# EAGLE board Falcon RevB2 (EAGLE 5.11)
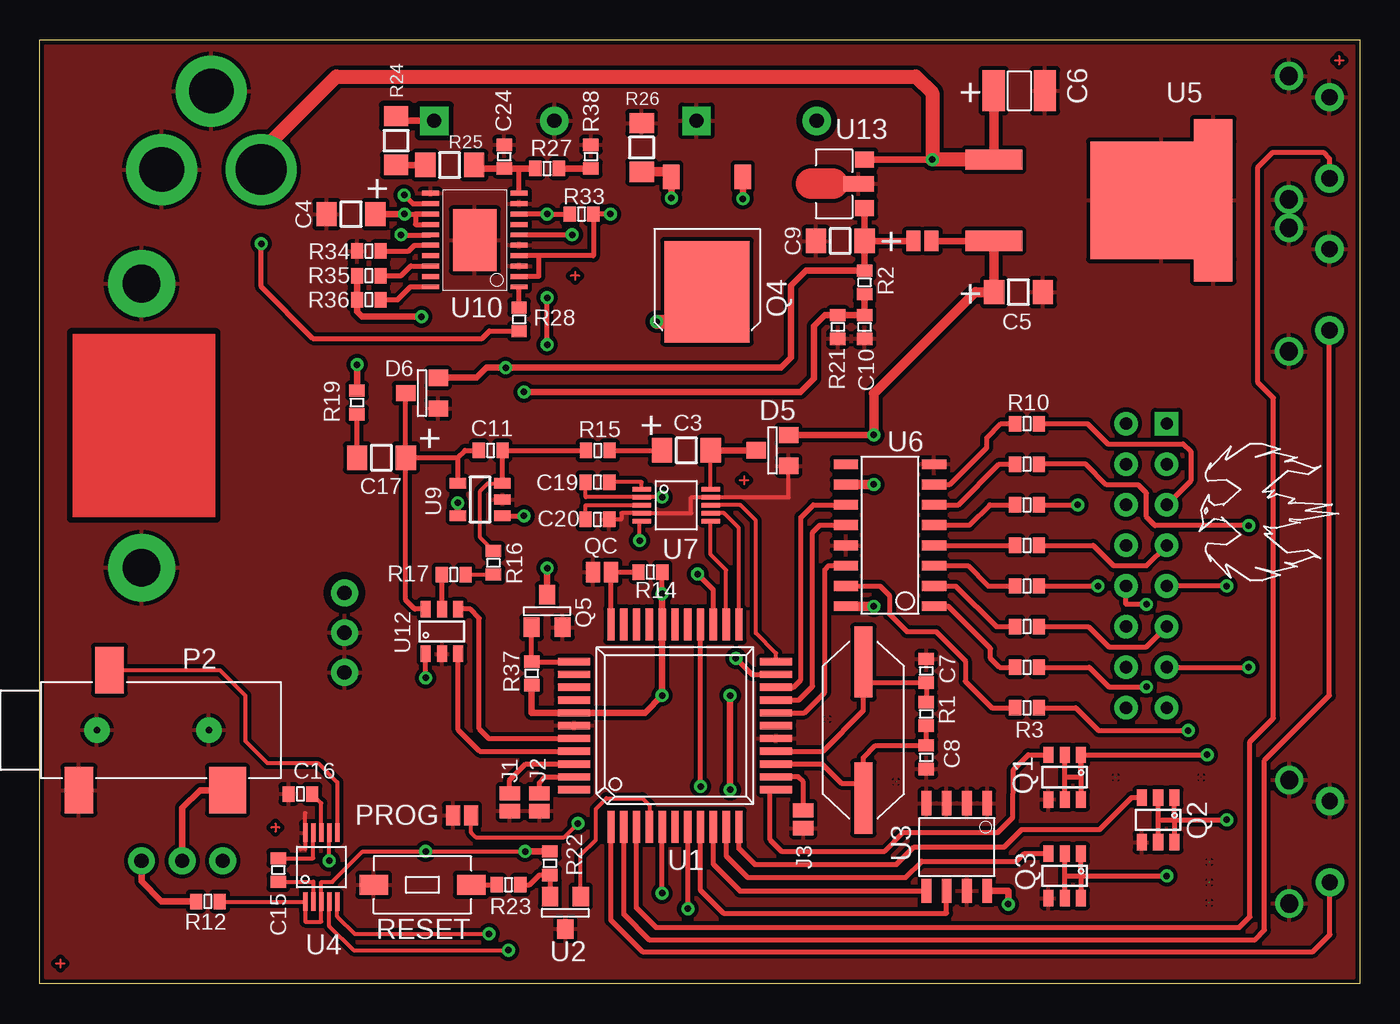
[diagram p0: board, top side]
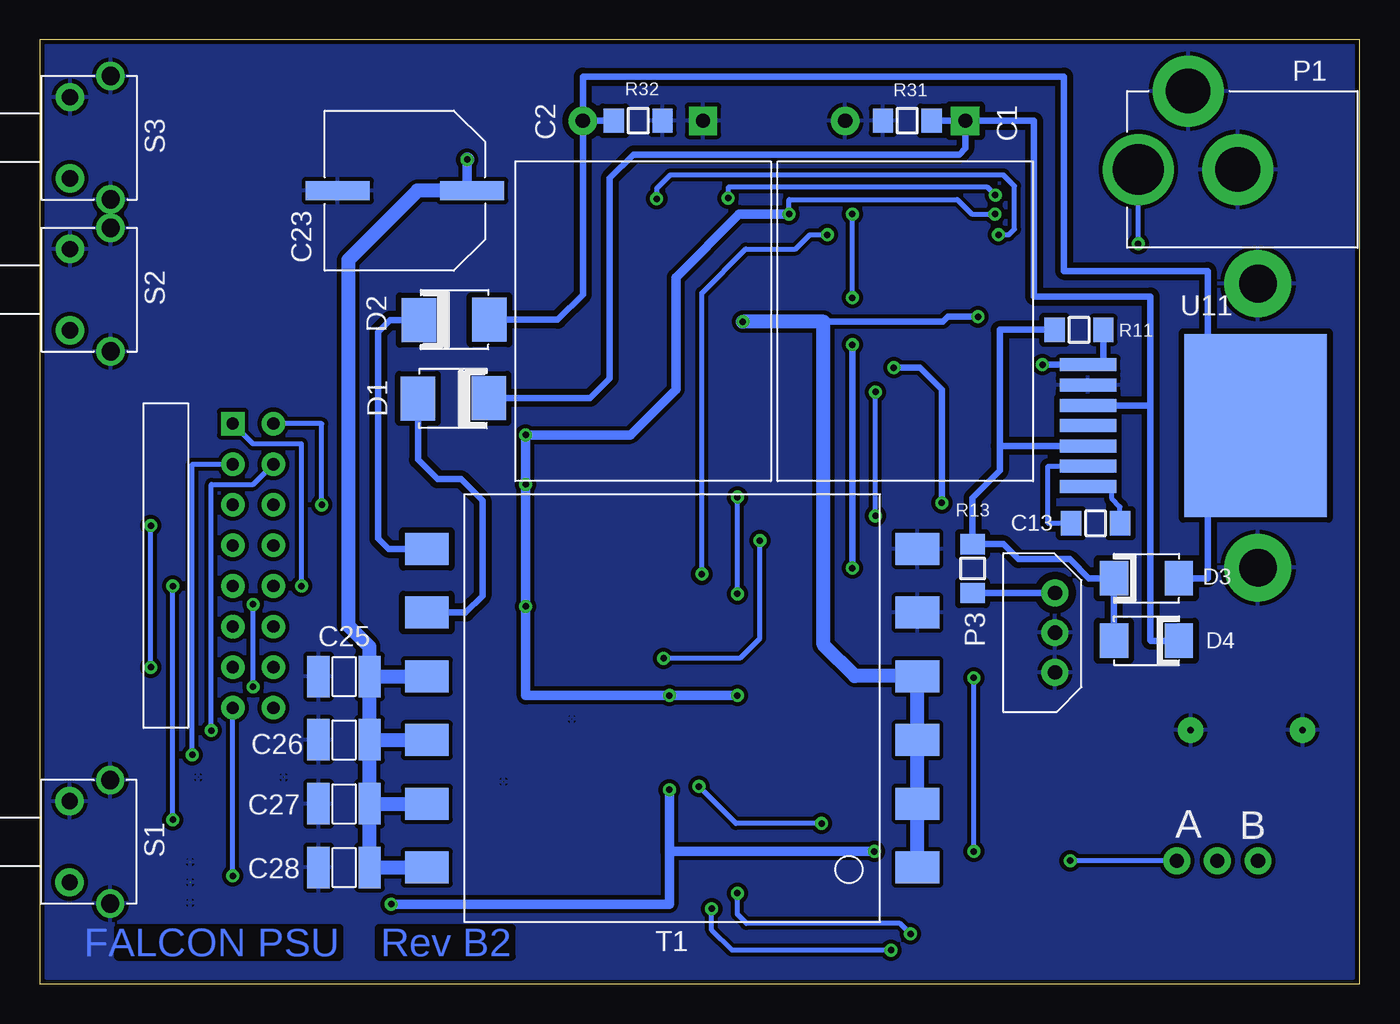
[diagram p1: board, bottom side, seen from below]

Size 82.55 x 59.05 mm. Coordinates in mm from the lower left corner, seen from the top.
Outline: 0,0 0,59.05 82.55,59.05 82.55,0 0,0
Copper layers (1*16): Top 0.035mm / dielectric 1.5mm / Bottom 0.035mm
Design rules "default *": minimum track width 10mil, minimum drill 1mil, track to track 8mil, track to pad 8mil, pad to pad 8mil, via to via 8mil, smd to smd 8mil, copper to edge 0mil, drill to drill 8mil, minimum pad ring 0mil, minimum via ring 0mil, stop-mask expansion 4mil, vias tented up to drill 20mil, thermal gap 10mil
tRestrict: area 23.7,53 to 25.6,55; area 47.9,53.3 to 49.3,54.7; area 21.5,53.6 to 23.1,55; area 18.2,23.6 to 19.9,25.3; area 1.9,29.1 to 11,40.8
bRestrict: area 53.3,40.1 to 55.6,43; area 57.7,40.1 to 60,43; area 57.7,35.2 to 60.1,38.1; area 53.3,35.2 to 55.7,38.1; area 56.9,26.1 to 59.8,28.3; area 47.9,53.3 to 49.3,54.7; area 23.7,53 to 25.6,55; area 1.9,29.1 to 11,40.8; area 15.1,35.7 to 18.8,36.7; area 15.1,34.4 to 18.8,35.4; area 15.1,33.2 to 18.8,34.1; area 15.1,31.9 to 18.8,32.9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; 55 lines

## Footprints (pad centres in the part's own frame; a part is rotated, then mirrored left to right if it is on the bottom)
EL_CAP_16X20RA = drill 0.889 pad 1.778 square: P$1 -12.548,3.759 | drill 0.889 pad 1.778 round: P$2 -12.548,-3.759
C1206 = smd 1.524 x 1.27: P$1 0,1.524; P$2 0,-1.524
1210 = smd 1.397 x 2.591: 1 -1.6,0; 2 1.6,0
C0603 = smd 0.762 x 0.965: P$1 -0.737,0; P$2 0.737,0
ELYC-10MM = smd 1.2 x 4: P$1 0,4.2; P$2 0,-4.2
SMB = smd 2.159 x 2.743: 1 -2.311,-0.127; 2 2.108,-0.102
SMA = smd 1.778 x 2.159: P$1 2.032,0; P$2 -2.032,0
SOT23 = smd 1.016 x 1.219: 1 -0.94,1.016; 2 0.991,1.016; 3 0.025,-1.016
TP = drill 0.889 pad 1.676 round: P$1 0,0
SMJUMP-S = smd 0.889 x 1.27: P$1 0.559,0; P$2 -0.559,0
2_56_MOUNTING = drill 2.362 pad 4.191 round: P$1 0,0
DIP16_RA = drill 0.762 pad 1.473 square: P$1 -8.89,-1.27 | drill 0.762 pad 1.473 round: P$2 -6.35,-1.27; P$3 -3.81,-1.27; P$4 -1.27,-1.27; P$5 1.27,-1.27; P$6 3.81,-1.27; P$7 6.35,-1.27; P$8 8.89,-1.27; P$9 8.89,1.27; P$10 6.35,1.27; P$11 3.81,1.27; P$12 1.27,1.27; P$13 -1.27,1.27; P$14 -3.81,1.27; P$15 -6.35,1.27; P$16 -8.89,1.27
CSM7 = smd 4.445 x 1.143: P$1 0,0; P$2 8.509,0
GNDVIA = drill 0.025 pad 0.046 round: P$1 0,0
2.5MMRA_PWR = drill 2.794 pad 4.445 round: P$1 0,0; P$3 3.099,-4.902 | drill 3.175 pad 4.445 round: P$2 6.223,0
3.5MMST_RA_SMT-3 = smd 1.803 x 2.896: P$1 5.131,3.759; P$2 3.226,-3.759 | smd 2.311 x 2.896: P$3 -4.166,3.759 | drill 0.406 pad 1.587 round: P$5 -2.997,0; P$6 4.013,0
SOT6 = smd 1.016 x 0.635: P$1 1.397,-1.016; P$2 1.397,0; P$3 -1.397,0; P$4 -1.397,-1.016; P$5 -1.397,1.016; P$6 1.397,1.016
TO-252 = smd 5.334 x 6.35: P$1 0,0.889 | smd 1.016 x 1.524: P$2 -2.235,-6.299; P$3 2.235,-6.299
C603_90 = smd 0.965 x 0.762: P$1 0,0.737; P$2 0,-0.737
SPST3X6 = smd 1.778 x 1.27: P$1 3.048,0; P$2 -3.048,0
TACTRA = drill 1.143 pad 1.778 round: P$1 1.346,-3.861; P$2 1.346,3.861 | drill 1.016 pad 1.778 round: P$3 -1.194,2.54; P$4 -1.194,-2.54
GA3459 = smd 2.743 x 2.007: P$1 -15.342,9.97; P$2 -15.342,5.982; P$3 -15.342,1.994; P$4 -15.342,-1.994; P$5 -15.342,-5.982; P$6 -15.342,-9.97; P$7 15.342,-9.97; P$8 15.342,-5.982; P$9 15.342,-1.994; P$10 15.342,1.994; P$11 15.342,5.982; P$12 15.342,9.97
QFP-44 = smd 0.457 x 2.007: 1 -4,-6.325; 2 -3.2,-6.325; 3 -2.4,-6.325; 4 -1.6,-6.325; 5 -0.8,-6.325; 6 0,-6.325; 7 0.8,-6.325; 8 1.6,-6.325; 9 2.4,-6.325; 10 3.2,-6.325; 11 4,-6.325; 23 4,6.325; 24 3.2,6.325; 25 2.4,6.325; 26 1.6,6.325; 27 0.8,6.325; 28 0,6.325; 29 -0.8,6.325; 30 -1.6,6.325; 31 -2.4,6.325; 32 -3.2,6.325; 33 -4,6.325 | smd 2.007 x 0.457: 12 6.325,-4; 13 6.325,-3.2; 14 6.325,-2.4; 15 6.325,-1.6; 16 6.325,-0.8; 17 6.325,0; 18 6.325,0.8; 19 6.325,1.6; 20 6.325,2.4; 21 6.325,3.2; 22 6.325,4; 34 -6.325,4; 35 -6.325,3.2; 36 -6.325,2.4; 37 -6.325,1.6; 38 -6.325,0.8; 39 -6.325,0; 40 -6.325,-0.8; 41 -6.325,-1.6; 42 -6.325,-2.4; 43 -6.325,-3.2; 44 -6.325,-4
SO-8 = smd 0.61 x 1.524: 1 -1.27,-2.743; 2 0,-2.743; 3 1.27,-2.743; 4 2.54,-2.743; 5 2.54,2.743; 6 1.27,2.743; 7 0,2.743; 8 -1.27,2.743
10UMAX = smd 0.279 x 1.143: P$1 -1,-2.16; P$2 -0.5,-2.16; P$3 0,-2.16; P$4 0.5,-2.16; P$5 1,-2.16; P$6 1,2.16; P$7 0.5,2.16; P$8 0,2.16; P$9 -0.5,2.16; P$10 -1,2.16
TO263 = smd 7.366 x 8.89: P$1 0,0 | smd 1.27 x 3.556: P$2 -2.54,-10.477; P$3 2.54,-10.477 | smd 10.16 x 2.413: P$4 0,3.239
SO-16 = smd 0.61 x 1.524: 1 -3.81,-2.819; 2 -2.54,-2.819; 3 -1.27,-2.819; 4 0,-2.819; 5 1.27,-2.819; 6 2.54,-2.819; 7 3.81,-2.819; 8 5.08,-2.819; 9 5.08,2.692; 10 3.81,2.692; 11 2.54,2.692; 12 1.27,2.692; 13 0,2.692; 14 -1.27,2.692; 15 -2.54,2.692; 16 -3.81,2.692
SOT23-5 = smd 1.016 x 0.635: 1 -1.397,1.016; 2 -1.397,0; 3 -1.397,-1.016; 4 1.397,-1.016; 5 1.397,1.016
TSSOP20_HEATSINK = smd 3.861 x 2.743: P$1 0,0 | smd 0.31 x 1.05: P$2 -2.925,-2.775; P$3 -2.275,-2.775; P$4 -1.625,-2.775; P$5 -0.975,-2.775; P$6 -0.325,-2.775; P$7 0.325,-2.775; P$8 0.975,-2.775; P$9 1.625,-2.775; P$10 2.275,-2.775; P$11 2.925,-2.775; P$12 2.925,2.775; P$13 2.275,2.775; P$14 1.625,2.775; P$15 0.975,2.775; P$16 0.325,2.775; P$17 -0.325,2.775; P$18 -0.975,2.775; P$19 -1.625,2.775; P$20 -2.275,2.775; P$21 -2.925,2.775
TO263-7 = smd 11.43 x 8.89: P$1 0,0 | smd 0.813 x 3.556: P$2 -2.54,-10.477; P$3 -1.27,-10.477; P$4 0,-10.477; P$5 1.27,-10.477; P$6 2.54,-10.477; P$7 -3.81,-10.477; P$8 3.81,-10.477
SOT-89 = smd 0.991 x 1.194: 1 -1.524,-1.829; 2 1.524,-1.829 | smd 0.991 x 1.905: 3 0,-1.448

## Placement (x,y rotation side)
C1  [EL_CAP_16X20RA]  28.42,41.45 270 bottom
C2  [EL_CAP_16X20RA]  44.83,41.45 270 bottom
C3  [C1206]  40.44,33.38 90 top
C4  [C1206]  19.46,48.16 90 top
C5  [C1206]  61.21,43.28 90 top
C6  [1210]  61.26,55.88 0 top
C7  [C0603]  55.45,19.58 90 top
C8  [C0603]  55.45,14.17 90 top
C9  [C1206]  50.06,46.48 90 top
C10  [C0603]  51.59,41.1 90 top
C11  [C0603]  28.19,33.38 0 top
C13  [C1206]  16.51,28.82 270 bottom
C15  [C0603]  14.91,7.12 90 top
C16  [C0603]  16.29,11.87 0 top
C17  [C1206]  21.36,32.92 90 top
C19  [C0603]  34.87,31.39 0 top
C20  [C0603]  34.87,29.06 0 top
C23  [ELYC-10MM]  59.72,49.63 270 bottom
C24  [C0603]  29.04,51.75 270 top
C25  [1210]  63.53,19.23 0 bottom
C26  [1210]  63.53,15.28 0 bottom
C27  [1210]  63.53,11.26 0 bottom
C28  [1210]  63.53,7.28 0 bottom
D1  [SMB]  56.59,36.75 0 bottom
D2  [SMB]  56.74,41.43 180 bottom
D3  [SMA]  13.34,25.37 0 bottom
D4  [SMA]  13.34,21.46 0 bottom
D5  [SOT23]  45.82,33.4 270 top
D6  [SOT23]  23.9,36.98 270 top
E$1  [TP]  19.05,21.97 0 top
E$2  [TP]  19.05,24.46 0 top
E$3  [TP]  19.05,19.48 0 top
E$4  [SMJUMP-S]  31.24,11.37 90 top
E$5  [SMJUMP-S]  29.39,11.37 90 top
E$6  [TP]  8.89,7.7 0 top
E$7  [SMJUMP-S]  55.21,46.48 180 top
E$8  [TP]  6.35,7.7 0 top
E$9  [TP]  11.43,7.7 0 top
E$10  [2_56_MOUNTING]  6.35,26.04 0 top
E$11  [PHOENIX_LOGO]  75.69,29.51 90 top
E$12  [DIP16_RA]  69.22,26.16 270 bottom
E$13  [CSM7]  51.51,11.62 90 top
E$14  [2_56_MOUNTING]  6.35,43.81 0 top
E$15  [SMJUMP-S]  35.17,25.76 180 top
E$16  [GNDVIA]  73.15,7.62 0 top
E$17  [GNDVIA]  73.15,6.35 0 top
E$18  [GNDVIA]  73.15,5.08 0 top
E$19  [GNDVIA]  67.31,12.93 0 top
E$20  [GNDVIA]  72.64,12.93 0 top
E$21  [GNDVIA]  49.28,16.56 0 top
E$22  [GNDVIA]  53.54,12.65 0 top
E$23  [SMJUMP-S]  47.75,10.3 90 top
E$24  [SMJUMP-S]  26.4,10.54 180 top
P1  [2.5MMRA_PWR]  7.62,50.95 180 bottom
P2  [3.5MMST_RA_SMT-3]  7.57,15.88 180 top
Q1  [SOT6]  64.11,12.93 270 top
Q2  [SOT6]  69.95,10.26 270 top
Q3  [SOT6]  64.11,6.76 270 top
Q4  [TO-252]  41.73,44.2 180 top
Q5  [SOT23]  31.75,23.32 180 top
R1  [C0603]  55.45,16.89 90 top
R2  [C0603]  51.59,43.89 90 top
R3  [C603_90]  61.75,17.27 90 top
R4  [C603_90]  61.75,19.81 90 top
R5  [C603_90]  61.75,22.35 90 top
R6  [C603_90]  61.75,24.89 90 top
R7  [C603_90]  61.75,27.43 90 top
R8  [C603_90]  61.75,29.97 90 top
R9  [C603_90]  61.75,32.51 90 top
R10  [C603_90]  61.75,35.05 90 top
R11  [C1206]  17.55,40.92 90 bottom
R12  [C0603]  10.5,5.16 180 top
R13  [C1206]  24.21,25.98 0 bottom
R14  [C0603]  38.19,25.76 180 top
R15  [C0603]  34.9,33.38 0 top
R16  [C0603]  28.37,26.34 90 top
R17  [C0603]  25.88,25.6 0 top
R19  [C0603]  19.84,36.37 270 top
R21  [C0603]  49.91,41.1 90 top
R22  [C0603]  31.9,7.54 90 top
R23  [C0603]  29.31,6.2 0 top
R24  [C1206]  22.28,52.76 180 top
R25  [C1206]  25.63,51.23 90 top
R26  [C1206]  37.64,52.32 0 top
R27  [C0603]  31.72,51.02 0 top
R28  [C0603]  29.97,41.58 270 top
R31  [C1206]  28.3,54 90 bottom
R32  [C1206]  45.12,54 90 bottom
R33  [C0603]  33.88,48.16 0 top
R34  [C0603]  20.57,45.85 180 top
R35  [C0603]  20.57,44.3 180 top
R36  [C0603]  20.57,42.8 180 top
R37  [C0603]  30.76,19.42 90 top
R38  [C0603]  34.47,51.75 90 top
RESET  [SPST3X6]  23.93,6.2 180 top
S1  [TACTRA]  79.5,8.89 0 bottom
S2  [TACTRA]  79.48,43.43 0 bottom
S3  [TACTRA]  79.48,52.93 0 bottom
T1  [GA3459]  43,17.25 180 bottom
U1  [QFP-44]  39.73,16.15 0 top
U2  [SOT23]  32.84,4.45 0 top
U3  [SO-8]  57.99,8.56 180 top
U4  [10UMAX]  17.6,7.3 0 top
U5  [TO263]  70.15,49.02 270 top
U6  [SO-16]  53.11,27.43 90 top
U7  [10UMAX]  39.8,29.95 270 top
U9  [SOT23-5]  27.53,30.3 180 top
U10  [TSSOP20_HEATSINK]  27.2,46.53 90 top
U11  [TO263-7]  6.5,34.92 270 bottom
U12  [SOT6]  25.15,22.05 90 top
U13  [SOT-89]  49.76,50.05 90 top

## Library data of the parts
C1 C2 E$1-E$11 E$13-E$15 E$23 E$24 P1 P2 RESET S1-S3 = WJC
C3-C5 C7-C11 C13 C15-C17 C19 C20 C24 D5 D6 E$16-E$22 Q1-Q3 Q5 R1-R17 R19 R21-R28 R31-R38 U2 U9 U12 = RF
C6 C23 C25-C28 Q4 U13 = SMD
D1-D4 = SMD-SPC
E$12 = pinhead
T1 = COILCRAFT
U1 U3-U7 U10 U11 = SMD-IC

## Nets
$24VDC: C6.1 C23.P$1 C25.2 C26.2 C27.2 C28.2 P1.P$2 R28.P$2 T1.P$9 T1.P$10 T1.P$11 U5.P$2 U13.2
$+175V: C1.P$1 D1.2 D4.P$1 R24.P$2 R31.P$2 U11.P$3
$-175V: C2.P$2 D2.1 D3.P$1 R32.P$1
$BIAS: C10.P$2 R2.P$1 R21.P$2 U9.1
$GND: C1.P$2 C2.P$1 C4.P$1 C5.P$2 C6.2 C7.P$2 C8.P$1 C9.P$1 C10.P$1 C16.P$1 C20.P$2 C23.P$2 C24.P$1 C25.1 C26.1 C27.1 C28.1 D5.2 D6.2 E$1.P$1 E$3.P$1 E$4.P$2 E$5.P$2 E$10.P$1 E$14.P$1 E$15.P$1 E$16.P$1 E$17.P$1 E$18.P$1 E$19.P$1 E$20.P$1 E$21.P$1 E$22.P$1 E$23.P$2 E$24.P$1 P1.P$1 P1.P$3 P2.P$1 P2.P$5 P2.P$6 Q1.P$1 Q2.P$1 Q3.P$1 Q5.1 R21.P$1 R26.P$1 R31.P$1 R32.P$2 R34.P$2 R38.P$2 RESET.P$1 S1.P$1 S1.P$2 S1.P$3 S2.P$1 S2.P$2 S2.P$3 S3.P$1 S3.P$2 S3.P$3 T1.P$5 T1.P$6 U1.16 U1.39 U2.3 U3.1 U3.2 U3.3 U3.4 U3.7 U4.P$10 U5.P$1 U5.P$4 U6.8 U6.13 U7.P$4 U7.P$9 U9.2 U10.P$1 U10.P$4 U10.P$6 U10.P$10 U10.P$12 U11.P$2 U12.P$3 U13.3
$VCC: C4.P$2 C5.P$1 C19.P$1 D5.1 E$7.P$2 R12.P$1 R14.P$1 R22.P$2 R33.P$2 R37.P$1 U1.29 U1.38 U3.8 U4.P$1 U4.P$3 U5.P$3 U6.10 U6.16 U7.P$2 U10.P$3 U10.P$5 U10.P$14 U10.P$15 U12.P$5
S$1: U1.4 U2.2
S$2: U1.5 U4.P$5
S$3: R24.P$1 R25.P$1
S$4: U1.8 U3.6
S$5: U1.7 U4.P$4
S$6: U1.9 U3.5
S$7: E$24.P$2 U1.26
S$8: R4.P$1 U6.1
S$9: Q3.P$4 U1.10
S$10: Q2.P$4 U1.11
S$11: R5.P$1 U6.2
S$12: R6.P$1 U6.3
S$13: R7.P$1 U6.4
S$14: R8.P$1 U6.5
S$15: R9.P$1 U6.6
S$16: R10.P$1 U6.7
S$17: R3.P$1 U6.15
S$18: E$12.P$15 R3.P$2
S$19: E$12.P$12 R4.P$2
S$20: E$12.P$6 R5.P$2
S$21: E$12.P$1 R6.P$2
S$22: E$12.P$4 R7.P$2
S$23: E$12.P$16 R8.P$2
S$24: E$12.P$7 R9.P$2
S$25: E$12.P$3 R10.P$2
S$26: E$12.P$2 Q1.P$2 Q1.P$3 Q1.P$5 Q1.P$6
S$27: Q1.P$4 U1.12
S$28: E$6.P$1 P2.P$3
S$29: C7.P$1 E$13.P$2 R1.P$2 U1.15
S$30: S1.P$4 U1.1
S$31: E$12.P$5 Q2.P$2 Q2.P$3 Q2.P$5 Q2.P$6
S$32: E$12.P$8 Q3.P$2 Q3.P$3 Q3.P$5 Q3.P$6
S$33: S2.P$4 U1.2
S$34: C8.P$2 E$13.P$1 R1.P$1 U1.14
S$35: S3.P$4 U1.3
S$36: U1.24 U7.P$6
S$37: U1.23 U7.P$7
S$38: U1.22 U7.P$8
S$39: U1.21 U7.P$5
S$40: C9.P$2 D6.1 E$7.P$1 R2.P$2 U9.5 U13.1
S$41: U1.20 U6.11
S$42: U1.19 U6.12
S$43: U1.18 U6.14
S$44: R11.P$2 R19.P$1 U11.P$7
S$45: R27.P$2 R38.P$1
S$46: E$9.P$1 U4.P$7
S$47: D2.2 T1.P$7
S$48: E$8.P$1 R12.P$2
S$49: E$15.P$2 R14.P$2 U1.33
S$50: C15.P$2 U4.P$9
S$51: C15.P$1 U4.P$2
S$52: C3.P$1 R15.P$2
S$53: E$2.P$1 R13.P$2
S$54: R28.P$1 U10.P$2
S$55: C3.P$2 D5.3 U7.P$10
S$56: P2.P$2 U4.P$6
S$57: C11.P$1 C17.P$2 D6.3 U9.4 U12.P$6
S$59: R17.P$1 U12.P$2
S$60: R22.P$1 R23.P$2 U2.1
S$61: C11.P$2 R15.P$1 R16.P$2 U9.3
S$65: R23.P$1 RESET.P$2
S$68: C13.P$1 U11.P$8
S$69: C13.P$2 U11.P$6
S$72: C16.P$2 U4.P$8
S$73: C17.P$1 R19.P$2
S$75: C19.P$2 U7.P$1
S$76: C20.P$1 U7.P$3
S$78: U1.40 U12.P$1
S$79: D1.1 T1.P$8
S$80: Q4.P$2 U10.P$16
S$81: C24.P$2 R25.P$2 R27.P$1 U10.P$11
S$82: Q4.P$1 R35.P$2 R36.P$2 T1.P$1 T1.P$2 T1.P$3 T1.P$4
S$83: U1.41 U12.P$4
S$84: E$23.P$1 U1.13
S$85: R16.P$1 R17.P$2
S$86: T1.P$12
S$87: R34.P$1 U10.P$17
S$88: E$5.P$1 U1.42
S$89: R35.P$1 U10.P$19
S$90: R36.P$1 U10.P$21
S$91: E$4.P$1 U1.43
S$92: D3.P$2 D4.P$2 R11.P$1 R13.P$1 U11.P$5
S$93: Q5.2 R37.P$2 U1.34
S$94: Q4.P$3 R26.P$2 U10.P$13
S$95: Q5.3 R33.P$1 U10.P$9
S$96: U1.25 U10.P$7

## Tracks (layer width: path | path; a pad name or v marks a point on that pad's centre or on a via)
$24VDC  (via drill 0.41 pad 0.81)
  Top 0.305: R28.P$2 28.12,40.84 27.66,40.39 17.07,40.39 13.84,43.61 v13.84,46.3
  Top 0.406: v55.82,51.58 U13.2
  Top 0.61: C6.1 59.68,55.88 U5.P$2
  Top 0.635: v55.82,51.58 55.8,51.59
  Top 0.889: U5.P$2 59.68,51.59 55.8,51.59 | v55.82,51.58 55.82,55.74 54.79,56.77 18.54,56.77 13.84,52.07 P1.P$2
  Bottom 0.305: v13.84,46.3 P1.P$2
  Bottom 0.61: 56.01,49.63 55.82,49.82 v55.82,51.57
  Bottom 0.889: 59.66,7.28 C28.2 61.95,7.28 61.95,11.27 | T1.P$10 58.34,15.28 C26.2 61.95,15.28 | T1.P$11 C27.2 61.95,11.27 | T1.P$9 58.34,19.23 C25.2 61.95,19.23 | 61.95,15.28 61.95,11.27 | 61.95,19.23 61.95,15.28 | 61.95,19.23 61.95,21.11 63.27,22.43 63.27,45.29 58.93,49.63 56.01,49.63 C23.P$1 | v55.82,51.58 v55.82,51.57
$+175V
  Top 0.406: R24.P$2 22.28,54 C1.P$1
  Bottom 0.406: D1.2 48.13,36.65 46.91,37.87 46.91,50.39 45.41,51.89 25.04,51.89 24.66,52.27 C1.P$1 | C1.P$1 R31.P$2 | C1.P$1 20.37,54 20.37,43 13.08,43 13.08,36.2 | D4.P$1 13.06,21.46 13.08,21.51 13.08,36.2 | 13.08,36.2 U11.P$3
$-175V
  Bottom 0.406: D2.1 50.16,41.55 48.59,43.13 C2.P$2 | C2.P$2 R32.P$1 | C2.P$2 48.59,56.77 18.49,56.77 18.49,44.6 9.5,44.6 9.5,25.38 D3.P$1
$BIAS  (via drill 0.41 pad 0.81)
  Top 0.305: U9.1 v30.28,29.29
  Top 0.406: R2.P$1 C10.P$2 R21.P$2 49.1,41.83 48.41,41.15 48.41,37.87 47.57,37.03 v30.28,37.03
  Bottom 0.305: v30.28,29.29 v30.28,37.03
$GND
  Top 0.254: 27.2,44.96 U10.P$1 | 16.59,10.69 16.6,10.68 U4.P$10 16.6,8.43 16.31,8.43 | C20.P$2 36.37,29.06 36.37,29.45 U7.P$4 40.74,29.45 40.74,30.45 U7.P$9 46.84,30.45 D5.2
  Top 0.305: U10.P$1 27.2,46.23
  pour Top (isolate 0.254): 0.38,0.38 0.38,58.67 82.17,58.67 82.17,0.38
  pour Bottom (isolate 0.254): 0.38,0.38 0.38,58.67 82.17,58.67 82.17,0.38
$VCC  (via drill 0.41 pad 0.81)
  Top 0.254: C19.P$1 34.14,30.45 U7.P$2 v38.92,30.45 | U1.38 | v30.35,8.28 v24.13,8.28 20.19,8.28 18.29,6.38 17.6,6.38 U4.P$3 17.6,3.89 16.6,3.89 U4.P$1 11.24,5.14 R12.P$1
  Top 0.305: U10.P$15 23.5,47.51 23.5,48.16 U10.P$14 v22.81,48.16 | v22.81,48.16 | U10.P$3 31.19,44.26 31.19,45.56 | 31.19,45.56 U10.P$5 | 31.19,45.56 34.62,45.56 R33.P$2 v35.69,48.16 | v38.92,24.4 R14.P$1 | v24.13,19.15 U12.P$5
  Top 0.406: v22.81,48.16 C4.P$2 | U5.P$3 E$7.P$2 | R37.P$1 30.76,16.94 U1.38 | v52.17,34.34 D5.1 | v38.92,24.4 U1.29 v38.92,18.03 37.85,16.95 U1.38 | U3.8 60.58,5.82 v60.58,4.98 | v43.18,12.14 v43.18,18.03 | v30.35,8.28 R22.P$2
  Top 0.61: U5.P$3 C5.P$1 | v52.17,34.34 52.17,36.93 | v52.17,31.24 U6.10 | v52.17,23.62 U6.16
  Top 0.635: C5.P$1 58.52,43.28 52.17,36.93
  Bottom 0.305: v22.81,48.16 24.26,48.16 25.17,49.07 35.69,49.07 v35.69,48.16 | v38.92,24.4 v38.92,30.45 | v24.13,8.28 v24.13,19.15
  Bottom 0.61: v35.69,48.16 38.81,48.16 42.77,44.2 42.77,37.19 45.62,34.34 v52.17,34.34 v52.17,31.24 v52.17,23.62 52.17,18.03 v43.18,18.03 v38.92,18.03 | v60.58,4.98 43.18,4.98 43.18,8.28 | 43.18,8.28 v43.18,12.14 | v30.35,8.28 43.18,8.28
S$1
  Top 0.254: U1.4 38.12,11.18 37.69,11.61 35.43,11.61 34.77,10.95 34.77,9.02 33.83,8.08 U2.2
S$2  (via drill 0.41 pad 0.81)
  Top 0.254: v28.09,3.12 19.68,3.12 18.6,4.21 U4.P$5
  Top 0.305: v38.92,5.66 U1.5
  Bottom 0.305: v28.09,3.12 28.75,3.79 38.35,3.79 38.92,4.36 v38.92,5.66
S$3
  Top 0.406: R24.P$1 R25.P$1
S$4
  Top 0.305: U3.6 56.72,4.42 42.75,4.42 41.33,5.84 U1.8
S$5  (via drill 0.41 pad 0.81)
  Top 0.254: v29.31,2.11 19.61,2.11 18.1,3.62 U4.P$4
  Top 0.305: v40.53,4.7 U1.7
  Bottom 0.305: v40.53,4.7 40.53,3.37 39.27,2.11 v29.31,2.11
S$6
  Top 0.305: U3.5 43.79,5.82 42.13,7.48 U1.9
S$7  (via drill 0.41 pad 0.81)
  Top 0.254: v33.66,10.03 32.79,9.17 27.25,9.17 26.98,9.45 26.98,10.54 E$24.P$2
  Top 0.305: v41.33,12.34 U1.26
  Bottom 0.305: v33.66,10.03 39.01,10.03 v41.33,12.34
S$8
  Top 0.305: U6.1 56.82,23.62 59.46,20.98 59.46,20.37 60.02,19.81 R4.P$1
S$9
  Top 0.305: U1.10 42.93,8 44.27,6.66 54.15,6.66 55.17,7.67 61.11,7.67 61.59,8.15 Q3.P$4
S$10
  Top 0.305: Q2.P$4 68.3,11.66 66.29,9.65 61.42,9.65 60.33,8.56 54.69,8.56 53.59,7.47 44.73,7.47 43.73,8.47 U1.11
S$11
  Top 0.305: U6.2 57.28,24.89 59.82,22.35 R5.P$1
S$12
  Top 0.305: U6.3 58.04,26.16 59.31,24.89 R6.P$1
S$13
  Top 0.305: U6.4 R7.P$1
S$14
  Top 0.305: U6.5 58.14,28.7 59.41,29.97 R8.P$1
S$15
  Top 0.305: U6.6 57.45,29.97 59.99,32.51 R9.P$1
S$16
  Top 0.305: U6.7 56.92,31.24 59.23,33.55 59.23,34.16 60.12,35.05 R10.P$1
S$17
  Top 0.305: U6.15 52.55,24.89 53.14,24.31 53.14,23.14 54.23,22.05 56.06,22.05 57.89,20.22 57.89,18.92 59.54,17.27 R3.P$1
S$18  (via drill 0.41 pad 0.81)
  Top 0.305: R3.P$2 64.8,17.27 66.22,15.85 v71.83,15.85
  Bottom 0.305: v71.83,15.85 71.83,31.24 69.22,31.24 E$12.P$15
S$19  (via drill 0.41 pad 0.81)
  Top 0.305: E$12.P$12 67.94,23.75 v69.22,23.75 | R4.P$2 65.63,19.81 66.85,18.59 v69.22,18.59
  Bottom 0.305: v69.22,18.59 v69.22,23.75
S$20
  Top 0.305: R5.P$2 65.58,22.35 66.85,21.08 69.22,21.08 E$12.P$6
S$21  (via drill 0.41 pad 0.81)
  Top 0.305: R6.P$2 v66.19,24.89
  Bottom 0.305: v66.19,24.89 66.19,33.78 69.22,33.78 E$12.P$1
S$22
  Top 0.305: R7.P$2 65.89,27.43 67.16,26.16 69.22,26.16 E$12.P$4
S$23  (via drill 0.41 pad 0.81)
  Top 0.305: R8.P$2 v64.92,29.97
  Bottom 0.305: v64.92,29.97 64.92,35.05 E$12.P$16
S$24  (via drill 0.41 pad 0.81)
  Top 0.305: R9.P$2 65.43,32.51 66.73,31.22 68.71,31.22 69.22,30.71 69.22,29.21 69.75,28.68 v75.62,28.68 | E$12.P$7 v75.62,19.81
  Bottom 0.305: v75.62,19.81 v75.62,28.68
S$25
  Top 0.305: R10.P$2 65.53,35.05 66.8,33.78 71.53,33.78 71.98,33.33 71.98,31.47 E$12.P$3
S$26  (via drill 0.41 pad 0.81)
  Top 0.305: Q1.P$5 Q1.P$6 | Q1.P$3 Q1.P$2 64.11,12.95 65.13,12.95 Q1.P$5 | Q1.P$5 v73.03,14.33
  Bottom 0.305: E$12.P$2 73.03,32.51 v73.03,14.33
S$27
  Top 0.305: Q1.P$4 61.82,14.33 60.88,13.39 60.86,10.41 59.92,9.47 54.03,9.47 52.86,8.31 46.38,8.31 45.67,9.02 45.67,12.15 U1.12
S$28
  Top 0.406: E$6.P$1 8.89,11 10.01,12.12 P2.P$3
S$29
  Top 0.305: U1.15 48.97,14.55 51.51,17.09 51.51,18.85 | 51.51,18.85 E$13.P$2 51.51,20.62 | R1.P$2 C7.P$1 51.51,18.85
S$30
  Top 0.305: S1.P$4 80.7,3.07 79.63,2.01 37.69,2.01 35.71,3.99 35.71,9.82 U1.1
S$31  (via drill 0.41 pad 0.81)
  Top 0.305: 70.97,10.26 Q2.P$5 | 70.97,10.26 Q2.P$6 | Q2.P$3 Q2.P$2 69.95,10.26 70.97,10.26 | v74.24,24.89 E$12.P$5 | 70.97,10.26 v74.24,10.26
  Bottom 0.305: v74.24,10.26 v74.24,24.89
S$32  (via drill 0.41 pad 0.81)
  Top 0.305: 65.13,6.76 Q3.P$5 | 65.13,6.76 Q3.P$6 | Q3.P$3 Q3.P$2 64.11,6.76 65.13,6.76 | 65.13,6.76 v70.48,6.76
  Bottom 0.305: v70.48,6.76 E$12.P$8
S$33
  Top 0.305: S2.P$4 80.67,18.03 76.61,13.97 76.61,3.35 76.02,2.77 38.1,2.77 36.52,4.34 U1.2
S$34
  Top 0.305: R1.P$1 C8.P$2 52.27,14.91 51.51,14.15 51.51,12.39 | 51.51,12.39 E$13.P$1 | U1.14 48.93,13.75 50.14,12.55 51.36,12.55 51.51,12.39
S$35
  Top 0.305: S3.P$4 80.67,51.64 80.29,52.02 77.11,52.02 76.2,51.1 76.2,37.62 77.17,36.65 77.17,16.61 75.69,15.14 75.69,4.19 75.03,3.53 38.53,3.53 37.31,4.75 37.31,9.82 U1.3
S$36
  Top 0.254: U1.24 42.93,25.88 41.96,26.85 U7.P$6
S$37
  Top 0.254: U1.23 43.73,28.51 42.79,29.45 U7.P$7
S$38
  Top 0.254: U1.22 46.05,20.68 44.78,21.95 44.78,28.98 43.81,29.95 U7.P$8
S$39  (via drill 0.41 pad 0.81)
  Top 0.254: U7.P$5 37.52,28.95 37.52,28.8 v37.52,27.74
  Top 0.305: U1.21 44.55,19.36 v43.54,20.37
  Bottom 0.305: v43.54,20.37 38.76,20.37 37.52,21.61 v37.52,27.74
S$40  (via drill 0.41 pad 0.81)
  Top 0.406: C9.P$2 U13.1 | C9.P$2 E$7.P$1 | C9.P$2 R2.P$2 47.93,44.63 46.99,43.69 46.99,39.19 46.35,38.56 v29.13,38.56 27.94,38.56 27.3,37.92 D6.1 | U9.5 v26.14,30.1
  Bottom 0.406: v26.14,30.1 26.14,37.19 27.51,38.56 v29.13,38.56
S$41
  Top 0.305: U1.20 47.13,18.55 47.6,19.02 47.6,29.18 48.39,29.97 U6.11
S$42
  Top 0.305: U1.19 47.47,17.75 48.34,18.62 48.34,28.25 48.79,28.7 U6.12
S$43
  Top 0.305: U6.14 49.35,26.16 49.1,25.91 49.1,18.24 47.82,16.95 U1.18
S$44  (via drill 0.41 pad 0.81)
  Top 0.406: R19.P$1 v19.84,38.73
  Bottom 0.406: v19.84,38.73 U11.P$7 16.03,38.61 R11.P$2
S$45
  Top 0.406: R27.P$2 R38.P$1
S$46  (via drill 0.41 pad 0.81)
  Top 0.254: v18.1,7.7 U4.P$7
  Bottom 0.305: E$9.P$1 v18.1,7.7
S$47
  Bottom 0.406: T1.P$7 60.74,27.22 61.39,27.86 61.39,40.79 60.66,41.53 D2.2
S$48
  Top 0.406: E$8.P$1 6.35,6.4 7.59,5.16 R12.P$2
S$49
  Top 0.305: R14.P$2 E$15.P$2 U1.33
S$50
  Top 0.254: C15.P$2 17.1,7.86 U4.P$9
S$51
  Top 0.254: C15.P$1 17.1,6.39 U4.P$2
S$52
  Top 0.305: R15.P$2 C3.P$1
S$53
  Bottom 0.406: E$2.P$1 R13.P$2
S$54
  Top 0.305: U10.P$2 R28.P$1
S$55
  Top 0.254: U7.P$10 C3.P$2
  Top 0.406: C3.P$2 D5.3
S$56
  Top 0.254: P2.P$2 11.25,19.63 12.85,18.03 12.85,15.19 14.22,13.82 17.4,13.82 18.6,12.61 U4.P$6
S$57
  Top 0.305: C17.P$2 26.14,32.92 | 26.14,32.92 26.59,33.38 C11.P$1 | 26.14,32.92 U9.4 | U12.P$6 23.44,23.44 22.89,24 C17.P$2 | C17.P$2 D6.3
S$58
  Top 0.127: 33.73,44.3 33.22,44.3
S$59
  Top 0.305: U12.P$2 R17.P$1
S$60
  Top 0.305: U2.1 R22.P$1 31.24,6.81 30.63,6.2 R23.P$2
S$61
  Top 0.254: U9.3 28.02,31.32 27.53,30.84 27.53,27.91 R16.P$2
  Top 0.305: R15.P$1 C11.P$2 U9.3
S$62
  Top 0.127: 33.48,44.55 33.48,44.04
S$63
  Top 0.127: 44.3,31.5 43.79,31.5
S$64
  Top 0.127: 44.04,31.75 44.04,31.24
S$65
  Top 0.305: RESET.P$2 R23.P$1
S$66
  Top 0.127: 14.99,9.78 14.48,9.78
S$67
  Top 0.127: 14.73,10.03 14.73,9.53
S$68
  Bottom 0.305: C13.P$1 14.99,29.84 15.49,30.35 15.49,30.99 U11.P$8
S$69
  Bottom 0.305: C13.P$2 19.48,28.82 19.48,32.38 U11.P$6
S$70
  Top 0.127: 1.52,1.27 1.02,1.27
S$71
  Top 0.127: 1.27,1.52 1.27,1.02
S$72
  Top 0.254: C16.P$2 17.6,11.3 U4.P$8
S$73
  Top 0.305: C17.P$1 R19.P$2
S$74
  Top 0.127: 81.03,57.78 81.53,57.78
S$75
  Top 0.254: C19.P$2 37.64,31.39 U7.P$1
S$76
  Top 0.254: C20.P$1 34.14,29.95 U7.P$3
S$77
  Top 0.127: 81.28,58.04 81.28,57.53
S$78
  Top 0.305: U1.40 28.08,15.35 27.48,15.95 27.48,22.89 26.92,23.44 U12.P$1
S$79
  Bottom 0.406: T1.P$8 55.92,23.23 54.86,24.28 54.86,30.23 56.21,31.57 57.68,31.57 58.9,32.79 D1.1
S$80  (via drill 0.41 pad 0.81)
  Top 0.305: v22.58,46.86 v22.59,46.86 U10.P$16
  Top 0.406: v43.97,49.12 Q4.P$2
  Bottom 0.305: v43.97,49.12 43.97,49.76 43.13,50.6 22.28,50.6 21.59,49.91 21.59,47.22 21.95,46.86 v22.58,46.86
S$81
  Top 0.305: 29.69,51.02 29.97,51.02 U10.P$11
  Top 0.406: R25.P$2 27.15,51.04 27.18,51.02 C24.P$2 | 29.69,51.02 C24.P$2 | C24.P$2 29.97,51.02 R27.P$1
S$82  (via drill 0.41 pad 0.81)
  Top 0.406: R35.P$2 R36.P$2 19.84,42.06 20.17,41.73 v23.86,41.73
  Top 0.889: v38.58,41.43 41.73,41.43 Q4.P$1
  Bottom 0.406: 33.53,41.43 26.06,41.43 25.76,41.73 v23.86,41.73
  Bottom 0.635: T1.P$4 27.75,19.25
  Bottom 0.889: T1.P$1 T1.P$2 T1.P$3 T1.P$4 | v38.58,41.43 33.53,41.43 33.53,21.21 31.57,19.25 27.75,19.25
S$83
  Top 0.305: U1.41 27.51,14.55 26.16,15.9 U12.P$4
S$84
  Top 0.305: U1.13 47.42,12.95 47.75,12.62 E$23.P$1
S$85
  Top 0.254: R17.P$2 R16.P$1
S$86
  Bottom 0.889: T1.P$12 59.6,7.28
S$87
  Top 0.305: R34.P$1 23.06,45.85 23.42,46.21 U10.P$17
S$88
  Top 0.305: E$5.P$1 29.39,12.76 30.38,13.75 U1.42
S$89
  Top 0.305: R35.P$1 22.58,44.3 23.19,44.91 U10.P$19
S$90
  Top 0.305: R36.P$1 22.38,42.8 23.19,43.61 U10.P$21
S$91
  Top 0.305: E$4.P$1 31.24,12.59 31.61,12.95 U1.43
S$92
  Bottom 0.406: D4.P$2 D3.P$2 16.94,25.38 18.14,26.57 21.34,26.57 22.28,27.51 R13.P$1 24.21,30.4 22.5,32.11 22.5,33.66 | R11.P$1 22.5,40.92 22.5,33.66 | 22.5,33.66 U11.P$5
S$93
  Top 0.305: U1.34 R37.P$2 Q5.2
S$94  (via drill 0.41 pad 0.81)
  Top 0.305: U10.P$13 23.33,48.81 v22.78,49.35
  Top 0.406: v39.5,49.16 Q4.P$3
  Top 0.61: Q4.P$3 39.5,50.8 R26.P$2
  Bottom 0.305: v22.78,49.35 23.27,49.84 39.5,49.84 v39.5,49.16
S$95  (via drill 0.41 pad 0.81)
  Top 0.305: v31.73,39.99 v31.73,42.93 | R33.P$1 v31.73,48.16 v31.72,48.16 U10.P$9
  Top 0.406: Q5.3 v31.73,26.01
  Bottom 0.305: v31.73,42.93 v31.73,48.16
  Bottom 0.406: v31.73,26.01 v31.73,39.99
S$96  (via drill 0.41 pad 0.81)
  Top 0.305: U1.25 42.13,24.65 v41.15,25.63 | v33.3,46.86 v33.29,46.86 U10.P$7
  Bottom 0.305: v41.15,25.63 41.15,43.23 38.41,45.97 35.28,45.97 34.39,46.86 v33.3,46.86
(copper drawn outside any net)
  shapes: Top area x1

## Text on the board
Bottom: Rev B2 | FALCON PSU
tPlace: + | + | + | + | + | + | QC | J1 | J2 | PROG | J3
bPlace: P3 | B | A
bStop: Rev B2 | FALCON PSU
